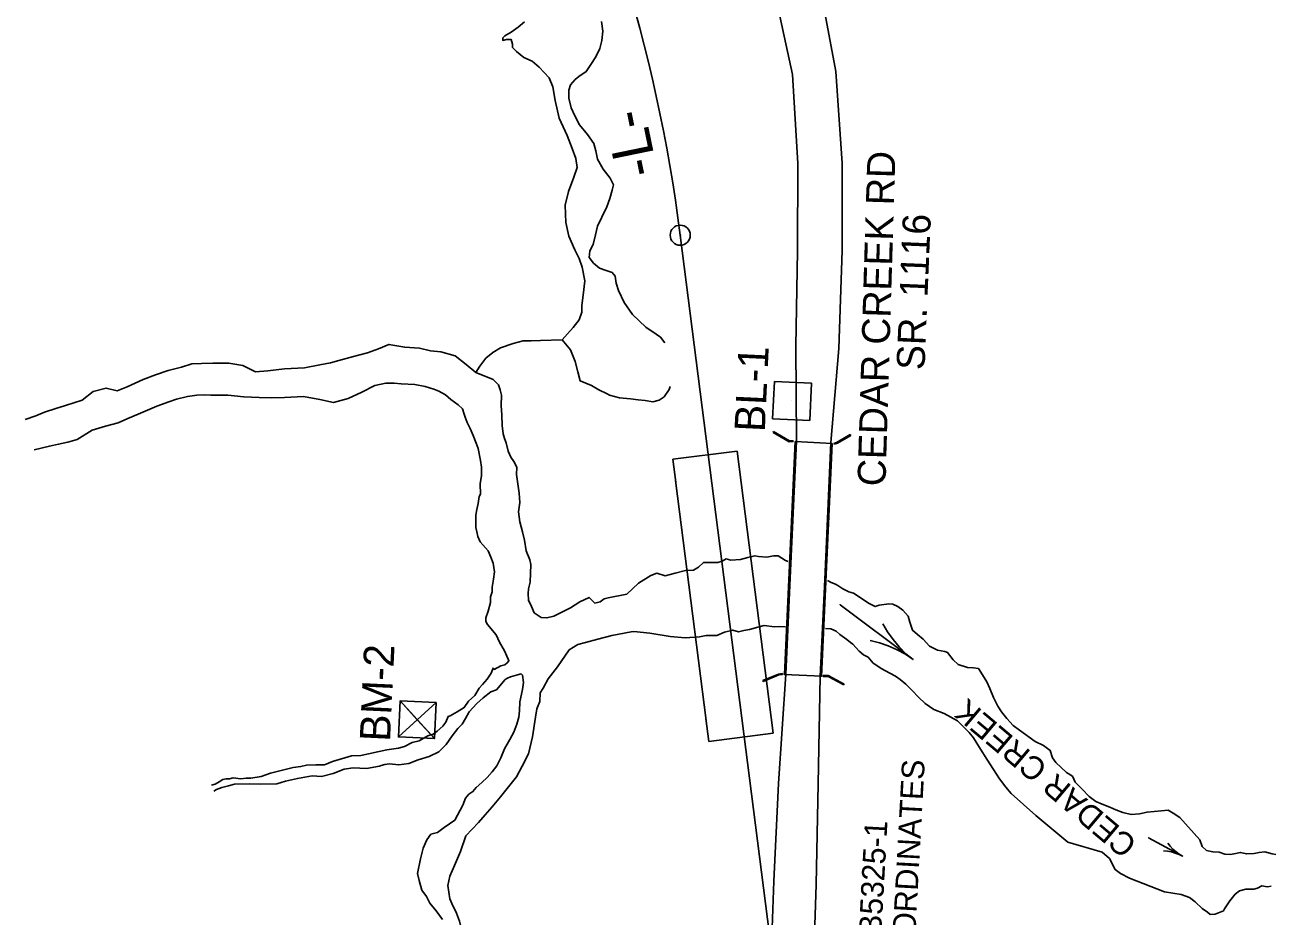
# Model space of a CAD drawing. Extents: x 2167298 to 2168977, y 841960 to 844561.
# Drawn here: x 2167692 to 2168338, y 843259 to 843720 of the extents above; entities that cross this region are included whole.
import ezdxf

# ---------------------------------------------------------------- set-up
doc = ezdxf.new("R2010")
doc.units = 0
for name, color, linetype in [('CTL Bench Mark CELL', 7, 'Continuous'), ('CTL Bench Mark Text', 7, 'Continuous'), ('CTL GPS Vertical Text', 7, 'Continuous'), ('CTL Supplemental Horizontal and Vertical CELL', 7, 'Continuous'), ('CTL Supplemental Horizontal and Vertical Text', 7, 'Continuous'), ('Default', 7, 'Continuous'), ('Exist Hydro River Flow Arrow CELL', 7, 'Continuous'), ('Exist Hydro Stream or Body of Water', 7, 'Continuous'), ('Exist Roads EOP', 7, 'Continuous'), ('Exist Structure Major Bridge WW', 7, 'Continuous'), ('Exist Structure Major Deck Tunnel Box Culvert', 7, 'Continuous'), ('Prop Horizontal Alignment', 7, 'Continuous')]:
    doc.layers.add(name, color=color, linetype=linetype)

msp = doc.modelspace()

# ---------------------------------------------------------------- linework, layer by layer
at = {"layer": 'CTL Bench Mark CELL'}
msp.add_line((2167894.71, 843361.22), (2167894.71, 843361.22), dxfattribs=at)
msp.add_lwpolyline([(2167885.81, 843370.95), (2167904.43, 843370.09), (2167903.57, 843351.47), (2167884.95, 843352.33)], close=True, dxfattribs=at)
for points in [[(2167904.43, 843370.09), (2167884.95, 843352.33), (2167894.69, 843361.21), (2167903.57, 843351.47), (2167885.81, 843370.95)], [(2167894.69, 843361.21), (2167904.43, 843370.09), (2167885.81, 843370.95), (2167894.69, 843361.21)], [(2167894.69, 843361.21), (2167884.95, 843352.33), (2167903.57, 843351.47), (2167894.69, 843361.21)]]:
    msp.add_lwpolyline(points, dxfattribs=at)
at = {"layer": 'CTL Supplemental Horizontal and Vertical CELL'}
msp.add_line((2168088.27, 843525.95), (2168088.27, 843525.95), dxfattribs=at)
msp.add_lwpolyline([(2168079.19, 843535.98), (2168098.4, 843535.08), (2168097.5, 843515.84), (2168078.29, 843516.74)], close=True, dxfattribs=at)
at = {"layer": 'Exist Hydro River Flow Arrow CELL'}
for p, q in [((2168132.03, 843406.48), (2168132.03, 843406.48)), ((2168281.36, 843295.5), (2168281.36, 843295.5))]:
    msp.add_line(p, q, dxfattribs=at)
for points in [[(2168135.27, 843410.79), (2168137.71, 843406.63), (2168140.53, 843402.62), (2168143.7, 843398.84), (2168147.12, 843395.35), (2168150.87, 843392.3), (2168113.19, 843420.65), (2168150.87, 843392.3), (2168146.9, 843395.06), (2168142.6, 843397.38), (2168138.09, 843399.37), (2168133.46, 843400.97), (2168128.79, 843402.17)], [(2168282.44, 843297.52), (2168283.73, 843295.93), (2168285.17, 843294.43), (2168286.74, 843293.05), (2168288.39, 843291.8), (2168290.16, 843290.76), (2168272.55, 843300.25), (2168290.16, 843290.76), (2168288.32, 843291.67), (2168286.37, 843292.37), (2168284.35, 843292.91), (2168282.31, 843293.29), (2168280.27, 843293.49)]]:
    msp.add_lwpolyline(points, dxfattribs=at)
at = {"layer": 'Exist Hydro Stream or Body of Water'}
for points in [[(2167950.09, 843721.86), (2167946.76, 843718.98), (2167943.15, 843716.39), (2167939.99, 843714.65), (2167938.97, 843713.61), (2167938.86, 843712.24), (2167940.86, 843712.7), (2167943.26, 843712.61), (2167943.87, 843710.24), (2167943.84, 843708.58), (2167945.98, 843706.5), (2167949.84, 843703.33), (2167954.09, 843701.49), (2167957.62, 843698.44), (2167962.78, 843692.86), (2167964.7, 843688.26), (2167966.03, 843681.12), (2167968.08, 843672.06), (2167972.13, 843663), (2167974.79, 843656.37), (2167976.69, 843651.24), (2167977.23, 843646.58), (2167975.61, 843641.47), (2167972.86, 843634.2), (2167971.17, 843627), (2167971.53, 843618.07), (2167972.99, 843611.07), (2167976.15, 843604.05), (2167978.33, 843599.46), (2167979.95, 843594.98), (2167981.31, 843587.96), (2167980.47, 843580.67), (2167979.76, 843575.28), (2167979.78, 843571.83), (2167978.28, 843567.88), (2167975.24, 843563.89), (2167972.36, 843560.66), (2167969.51, 843557.55)], [(2167978.25, 843693.48), (2167982, 843696.1), (2167984.46, 843699.74), (2167986.9, 843703.67), (2167989.1, 843708.11), (2167990.02, 843712.12), (2167990.65, 843717.03), (2167989.91, 843722.04)], [(2168005.9, 843570.68), (2168001.56, 843576.87), (2167998.73, 843583), (2167997.53, 843586.82), (2167996.93, 843590.32), (2167995.35, 843592.23), (2167992.27, 843593.34), (2167988.92, 843594.54), (2167985.76, 843597.17), (2167983.47, 843600.03), (2167983.86, 843603.49), (2167985.62, 843606.83), (2167986.76, 843611.77), (2167987.84, 843616.18), (2167990.14, 843620.8), (2167992.59, 843626.29), (2167994.15, 843630.61), (2167995.43, 843634.81), (2167996.14, 843637.63), (2167994.32, 843641.08), (2167990.74, 843645.72), (2167987.76, 843650.82), (2167986.9, 843655.14), (2167985.87, 843658.9), (2167982.62, 843663.67), (2167978.47, 843668.53), (2167976.04, 843673.31), (2167974.29, 843677.45), (2167973.09, 843682.3), (2167972.99, 843686.45), (2167973.89, 843689.31), (2167976.25, 843691.94), (2167978.25, 843693.48)], [(2168005.9, 843570.68), (2168012.8, 843564.03)], [(2168012.8, 843564.03), (2168018.15, 843560.45), (2168020.33, 843558.84), (2168022.55, 843555.99)], [(2167692.02, 843516.38), (2167697.6, 843518.26), (2167702.15, 843520.18), (2167707.97, 843522.06), (2167712.93, 843523.5), (2167721.62, 843526.35), (2167727.15, 843530.89), (2167733.87, 843532.55), (2167739.59, 843531.19), (2167744.75, 843533.29), (2167753.12, 843537), (2167759.4, 843539.37), (2167766.05, 843541.66), (2167772.85, 843543.37), (2167778.14, 843545.14), (2167783.15, 843545.28), (2167789.12, 843545.41), (2167797.32, 843545.42), (2167804.64, 843544.3), (2167811.15, 843541.03), (2167817.41, 843541.43), (2167826.04, 843542.44), (2167836.42, 843543.07), (2167844.3, 843544.57), (2167849.88, 843545.55), (2167854.1, 843546.83), (2167861.78, 843548.94), (2167868.93, 843550.85), (2167874.62, 843552.91), (2167880.07, 843555.18), (2167888.19, 843553.71), (2167895.85, 843553.13), (2167901.59, 843551.78), (2167906.85, 843551.36), (2167914.2, 843549.29), (2167920.04, 843544.76), (2167924.93, 843540.7)], [(2167924.93, 843540.7), (2167927.04, 843543.88), (2167930.06, 843547.97), (2167933.74, 843550.88), (2167937.69, 843553.35), (2167944.2, 843555.67), (2167949.37, 843557.01), (2167953.54, 843557.06), (2167958.43, 843557.09), (2167969.51, 843557.55)], [(2167969.51, 843557.55), (2167973.93, 843552.38), (2167976.22, 843546.28), (2167977.62, 843540.89), (2167978.82, 843536.33), (2167984.64, 843533.92), (2167988.56, 843531.75), (2167992.81, 843529.66), (2167993.96, 843528.85), (2167999.25, 843527.46), (2168004.95, 843527.04)], [(2167924.93, 843540.7), (2167933.96, 843537.02), (2167936.62, 843534.28), (2167937.54, 843531.66), (2167938.3, 843528.85), (2167938.03, 843523.56), (2167938.42, 843518.63), (2167938.56, 843513.33), (2167939, 843509.02), (2167939.78, 843506.51), (2167940.6, 843504.21), (2167941.58, 843499.9), (2167943.07, 843496.86), (2167944.53, 843494.66), (2167946.17, 843491.76), (2167946.03, 843487.87), (2167947.37, 843478.22), (2167947.77, 843473.39), (2167947.03, 843468.64), (2167947.68, 843463.42), (2167948.99, 843458.37), (2167950.11, 843453.98), (2167950.93, 843448.52), (2167952.8, 843443.77), (2167953.42, 843441.5), (2167952.96, 843432.31), (2167952.21, 843428.88), (2167951.93, 843426.45), (2167952.18, 843423.05), (2167953.69, 843419.8), (2167955.13, 843416.5), (2167958.66, 843414.12), (2167961.65, 843413.81), (2167965.29, 843414.78), (2167968.63, 843416.38), (2167973.92, 843419.06), (2167978.69, 843422.15), (2167983.43, 843424.38), (2167986.44, 843421.52), (2167989.15, 843422.11), (2167991.29, 843423.68), (2167993.41, 843424.13)], [(2167696.74, 843500.63), (2167704.61, 843502.65), (2167709.34, 843503.59), (2167714.11, 843504.68), (2167718.93, 843505.99), (2167726.77, 843510.9), (2167733.66, 843512.89), (2167740.1, 843514.64), (2167745.16, 843516.84), (2167750.49, 843519.15), (2167760.17, 843523.16), (2167766.38, 843525.44), (2167770.28, 843526.79), (2167775.89, 843528.21), (2167780.73, 843528.88), (2167784.58, 843529.14), (2167787.97, 843528.98), (2167796.77, 843528.84), (2167805.1, 843528.12), (2167812.97, 843527.63), (2167819.6, 843527.62), (2167826.09, 843527.78), (2167835.99, 843528.15), (2167844.27, 843526.72), (2167851.39, 843525.21), (2167858.91, 843527.28), (2167866.06, 843530.43), (2167872.84, 843533.84), (2167878.37, 843535.1), (2167882.79, 843535.2), (2167886.42, 843534.76), (2167893.5, 843534.39), (2167898.81, 843533.32), (2167903.33, 843532), (2167905.77, 843530.97), (2167909.33, 843529.13), (2167911.96, 843526.67)], [(2168025.44, 843533.35), (2168024.83, 843531.84), (2168022.32, 843528.13), (2168019.64, 843526.36), (2168016.4, 843525.53), (2168012.43, 843526.09), (2168008.91, 843526.46), (2168004.95, 843527.04)], [(2167911.96, 843526.67), (2167915.82, 843523.96), (2167918.04, 843521.91), (2167918.9, 843519.11), (2167919.41, 843517.63), (2167920.51, 843514.79), (2167922.01, 843511.65), (2167923.58, 843508.11), (2167925.09, 843504.08), (2167926.24, 843501.36), (2167927.4, 843495.21), (2167927.94, 843491.68), (2167927.95, 843487.47), (2167927.18, 843483.07), (2167927.42, 843477.84), (2167926.61, 843476.49), (2167926.23, 843473.02), (2167925.42, 843469.78), (2167924.98, 843466.85), (2167924.87, 843464.1), (2167924.97, 843460.58), (2167925.51, 843458.39), (2167926.02, 843455.97), (2167927.12, 843453.06), (2167931.3, 843448.5), (2167932.74, 843445.27), (2167933.9, 843442.08), (2167934.62, 843437.62), (2167934.07, 843433.79), (2167933.31, 843429.76), (2167933.44, 843427.36), (2167932.49, 843424.72), (2167932.48, 843421.81), (2167931.35, 843417.31), (2167930.14, 843413.83), (2167930.19, 843411.91), (2167930.93, 843410.39), (2167935.41, 843405.02), (2167937.18, 843401.24), (2167939.76, 843396.78), (2167940.98, 843394.11), (2167941.61, 843392.55)], [(2168086.38, 843443.03), (2168085, 843443.56), (2168081.15, 843445.84), (2168078.82, 843445.93), (2168075.25, 843445.25), (2168070.95, 843445.57), (2168069.18, 843445.95), (2168065.51, 843444.99), (2168061.67, 843443.99), (2168056.68, 843443.75), (2168054.22, 843444.42), (2168052.19, 843443.14), (2168049.92, 843442.42), (2168046.47, 843442.44), (2168042.56, 843442.45)], [(2168002.89, 843426.13), (2168008.94, 843431.78), (2168015.38, 843435.69), (2168018.54, 843436.94), (2168022.76, 843435.52), (2168028.01, 843436.89), (2168033.32, 843438.4), (2168037.46, 843438.53), (2168040.08, 843439.97), (2168042.56, 843442.45)], [(2168120.17, 843426.6), (2168117.75, 843427.39), (2168114.53, 843428.81), (2168112.05, 843430.66), (2168110.72, 843431.35), (2168108.52, 843432.12), (2168106.66, 843433.09)], [(2168002.89, 843426.13), (2167993.41, 843424.13)], [(2168120.17, 843426.6), (2168125.02, 843423.3), (2168127.76, 843421.45), (2168131.22, 843419.69), (2168133.35, 843420.37), (2168138.32, 843421.1)], [(2168140.44, 843420.89), (2168138.32, 843421.1)], [(2168140.44, 843420.89), (2168142.95, 843419.71), (2168145.58, 843417.89), (2168148.32, 843414.74), (2168149.28, 843411.63), (2168150.61, 843407.45), (2168153.22, 843405.3), (2168156.06, 843402.87), (2168159.28, 843399.3), (2168163.47, 843397.22), (2168167.32, 843396.47), (2168168.75, 843395.89), (2168171.63, 843392.14), (2168174.16, 843389.75), (2168179.06, 843388.15), (2168182.12, 843388.12), (2168184.66, 843387.71), (2168186.68, 843384.37), (2168189.07, 843380.83), (2168190.47, 843377.34), (2168192.51, 843372.74), (2168194.64, 843368.16)], [(2167995.2, 843404.71), (2167988.02, 843402.84), (2167981.54, 843401.15), (2167977.65, 843400.14), (2167973.11, 843397.32), (2167967.18, 843388.51), (2167962.29, 843382.33), (2167959.76, 843377.5), (2167958.16, 843375.04), (2167958.06, 843370.7), (2167956.54, 843366.91)], [(2168005.14, 843406.72), (2167995.2, 843404.71)], [(2168040.55, 843404.11), (2168033.17, 843403.52), (2168025.37, 843404.23), (2168014.86, 843405.98), (2168006.55, 843406.86), (2168005.14, 843406.72)], [(2168040.55, 843404.11), (2168044.03, 843404.79), (2168047.43, 843404.74), (2168049.46, 843404.73), (2168053.44, 843406.5), (2168057.68, 843407.51), (2168060.62, 843406.68), (2168063.37, 843407.25), (2168066.3, 843407.91), (2168070.59, 843409.02), (2168074, 843409.9), (2168079.34, 843409.29), (2168081.73, 843409.35), (2168084.9, 843409.21)], [(2168105.57, 843408.28), (2168108.46, 843408.15), (2168111.08, 843406.9), (2168113.08, 843405.29), (2168116.59, 843402.6), (2168118.52, 843401.21), (2168119.72, 843400.19)], [(2168134.66, 843387.45), (2168130.34, 843390.53), (2168127.61, 843393.56), (2168125.34, 843394.82), (2168122.98, 843396.68), (2168119.72, 843400.19)], [(2167937.83, 843389), (2167939.9, 843389.58), (2167941.18, 843390.56), (2167942.09, 843391.59), (2167941.61, 843392.55)], [(2167937.83, 843389), (2167934.49, 843387.26), (2167933.83, 843387.94), (2167932.85, 843385.34), (2167930.77, 843382.11), (2167928.38, 843379.42), (2167926.66, 843377.6), (2167924.46, 843373.66), (2167921.09, 843370.87), (2167919, 843367.53), (2167915.32, 843365.28), (2167911.69, 843363.31), (2167910.61, 843362.98), (2167909.52, 843359.93), (2167907.87, 843357.86), (2167904.96, 843355.33), (2167902.86, 843353.71), (2167900.16, 843352.85), (2167895.62, 843350.39), (2167892.12, 843349.4)], [(2168136.34, 843386.67), (2168134.66, 843387.45)], [(2168179.87, 843354.63), (2168173.76, 843360.62), (2168166.96, 843364.49), (2168161.66, 843366.58), (2168157.17, 843369.68), (2168153.76, 843372.87), (2168150.46, 843376.26), (2168147.16, 843379.52), (2168144.2, 843381.94), (2168141.75, 843383.79), (2168136.34, 843386.67)], [(2167895.2, 843340.44), (2167900.91, 843342.18), (2167905.77, 843344.57), (2167909.63, 843348.46), (2167912.77, 843352.84), (2167915.73, 843356.65), (2167917.89, 843358.89), (2167919.54, 843361.88), (2167921.55, 843365.31), (2167925.42, 843369.69), (2167928.77, 843372.58), (2167932.74, 843375.65), (2167935.62, 843376.71), (2167940.04, 843382)], [(2167947.68, 843370.45), (2167949.03, 843376.76), (2167949.64, 843380.52), (2167949.02, 843384.2), (2167948.32, 843384.89), (2167946.42, 843384.39), (2167942.82, 843383.44), (2167941.26, 843382.65), (2167940.04, 843382)], [(2167914.14, 843309.37), (2167918.3, 843317.12), (2167919.66, 843320.66), (2167921.39, 843322.76), (2167923.43, 843324.08), (2167925.16, 843326.29), (2167928.1, 843328.75), (2167930.81, 843331.34), (2167933.43, 843334.25), (2167935.82, 843337.43), (2167937.84, 843341.52), (2167939.82, 843346.23), (2167942.53, 843351.08), (2167944.53, 843354.8), (2167946.17, 843358.87), (2167947.22, 843362.54), (2167947.55, 843365.87), (2167947.68, 843370.45)], [(2167956.54, 843366.91), (2167955.7, 843362.51), (2167954.16, 843352.39), (2167952.19, 843343.58), (2167948.92, 843337.28), (2167945.98, 843331.7), (2167937.73, 843321.33), (2167933.37, 843316.25), (2167929.73, 843312.01), (2167926.3, 843308.06), (2167919.76, 843301.26)], [(2168194.64, 843368.16), (2168196.49, 843365.23), (2168199.4, 843361.93), (2168202.57, 843358.19), (2168205.87, 843355.84)], [(2168179.87, 843354.63), (2168182.16, 843351.81), (2168185.78, 843346), (2168188.92, 843340.78), (2168192.48, 843335.5), (2168195.52, 843330.76), (2168198.76, 843326.45), (2168201.48, 843323.17)], [(2168205.87, 843355.84), (2168213.99, 843350.05), (2168218.25, 843347.89), (2168221.64, 843345.33), (2168222.85, 843341.47), (2168224.72, 843339.05), (2168230.19, 843333.88), (2168233.24, 843332.15), (2168234.62, 843328.98), (2168238.25, 843325.28), (2168241.84, 843321.55), (2168245.29, 843319), (2168248.58, 843317.58)], [(2167788.33, 843327.34), (2167790.32, 843327.91), (2167792.38, 843329.06), (2167794.28, 843330.34), (2167795.95, 843330.62), (2167797.71, 843330.63), (2167799.61, 843331.13), (2167803.57, 843330.66), (2167806.24, 843331.01), (2167808.65, 843331), (2167814.07, 843331.95), (2167818.91, 843333.54), (2167824.3, 843334.95), (2167828.51, 843336.05), (2167830.63, 843336.56), (2167834.56, 843337.14), (2167837.52, 843337.74), (2167842.23, 843337.92), (2167846.78, 843337.99), (2167850.89, 843339.62), (2167860.79, 843342.56), (2167865.61, 843342.82), (2167878.96, 843345.62), (2167884.97, 843346.53), (2167888.12, 843347.39)], [(2167888.12, 843347.39), (2167892.12, 843349.4)], [(2167890.37, 843338.69), (2167895.2, 843340.44)], [(2167890.37, 843338.69), (2167885.18, 843337.94), (2167880.4, 843338.45), (2167877.98, 843338.1), (2167875.99, 843337.5), (2167875.26, 843337.17), (2167868.48, 843336.1), (2167861.49, 843336.39), (2167856.89, 843335.71), (2167851.24, 843333.37), (2167845.15, 843331.94), (2167840.34, 843332.22), (2167832.81, 843330.8), (2167826.59, 843329.43), (2167822.07, 843328.07), (2167813.7, 843327.91), (2167808.11, 843328.16), (2167800.29, 843327.91), (2167797.24, 843327.15), (2167793.69, 843326.22), (2167790.9, 843325.13), (2167789.51, 843324.32)], [(2168201.48, 843323.17), (2168214.28, 843311.74), (2168230.88, 843297.96), (2168248.59, 843292.87), (2168252.32, 843289.53), (2168255.24, 843283.8), (2168258.05, 843281.84), (2168262.73, 843279.33), (2168280.77, 843272.36), (2168289.34, 843270.99), (2168293.68, 843269.31), (2168296.57, 843267.15), (2168300.22, 843263.78), (2168303.07, 843261.82), (2168304.3, 843260.57), (2168306.96, 843260.8), (2168311.31, 843262.43), (2168311.76, 843263.44), (2168314.57, 843267.71), (2168317.25, 843271.04), (2168319.48, 843272.83), (2168322.86, 843273.72)], [(2168317.6, 843292.11), (2168314.65, 843291.61), (2168311.91, 843291.8), (2168308.98, 843292.85), (2168305.76, 843293.01), (2168302.54, 843293.63), (2168300.22, 843295.68), (2168299.13, 843299.18), (2168288.76, 843310.69), (2168285.35, 843312.92), (2168282.7, 843314.42), (2168275.41, 843313.88), (2168271.78, 843313.5), (2168267.87, 843312.58), (2168263.61, 843312.26), (2168259.21, 843313.38), (2168255.61, 843314.68), (2168252.46, 843315.99), (2168248.58, 843317.58)], [(2167907.73, 843258.06), (2167904.42, 843262.46), (2167901.24, 843266.42), (2167899.43, 843269.93), (2167897.04, 843273.21), (2167895.59, 843278.19), (2167894.81, 843281.76), (2167896.35, 843289.36), (2167897.69, 843294.83), (2167899.67, 843299.2), (2167901.74, 843302.08), (2167905.14, 843302.96), (2167908.64, 843305.5), (2167914.14, 843309.37)], [(2167919.76, 843301.26), (2167917.03, 843293.13), (2167913.93, 843285.98), (2167911.6, 843280.38), (2167910.53, 843275.5), (2167911.52, 843268.76), (2167912.6, 843266.26), (2167915.01, 843261.26)], [(2168317.6, 843292.11), (2168319.96, 843292.7), (2168323.32, 843291.89), (2168327.09, 843292.03), (2168329.66, 843292.7), (2168332.71, 843293.05), (2168336.37, 843291.99), (2168338.39, 843291.65)], [(2168335.88, 843275.28), (2168334.08, 843274.93), (2168331.07, 843275.49), (2168328.9, 843274.17), (2168326.9, 843273.61), (2168322.86, 843273.72)], [(2167915.01, 843261.26), (2167916.45, 843257.13), (2167917.63, 843252.79), (2167916.61, 843249.72), (2167916.58, 843246.42), (2167916.83, 843243.68), (2167918.83, 843239.9), (2167917.17, 843236.14), (2167915.45, 843232.08), (2167913.97, 843229.18), (2167911.58, 843226.81)]]:
    msp.add_lwpolyline(points, dxfattribs=at)
at = {"layer": 'Exist Roads EOP'}
for points in [[(2168088.8, 842986.5), (2168090.54, 843034.94), (2168092.62, 843085.63), (2168094.79, 843136.47), (2168097.17, 843179.92), (2168099.2, 843228.96), (2168100.75, 843276.01), (2168101.9, 843328.13), (2168102.88, 843383.52), (2168105.26, 843433.67), (2168108.45, 843504.42), (2168112.55, 843553.1), (2168114.28, 843603.6), (2168114.19, 843648.77), (2168111.04, 843696.23), (2168101.28, 843747.73)], [(2168088.8, 842986.5), (2168090.54, 843034.94), (2168092.62, 843085.63), (2168094.79, 843136.47), (2168097.17, 843179.92), (2168099.2, 843228.96), (2168100.75, 843276.01), (2168101.9, 843328.13), (2168102.88, 843383.52), (2168105.26, 843433.67), (2168108.45, 843504.42), (2168112.55, 843553.1), (2168114.28, 843603.6), (2168114.19, 843648.77), (2168111.04, 843696.23), (2168101.28, 843747.73)], [(2168066.47, 842986.79), (2168068.78, 843034.77), (2168070.69, 843085.52), (2168073.1, 843137.29), (2168075.19, 843180.69), (2168077.23, 843229.63), (2168078.87, 843277.87), (2168081.38, 843328.25), (2168085.18, 843384.71), (2168087.31, 843434.46), (2168090.6, 843505.16), (2168090.32, 843554.22), (2168091.17, 843603.38), (2168091.32, 843648.61), (2168088.6, 843694.65), (2168078.62, 843740.74)], [(2168066.47, 842986.79), (2168068.78, 843034.77), (2168070.69, 843085.52), (2168073.1, 843137.29), (2168075.19, 843180.69), (2168077.23, 843229.63), (2168078.87, 843277.87), (2168081.38, 843328.25), (2168085.18, 843384.71), (2168087.31, 843434.46), (2168090.6, 843505.16), (2168090.32, 843554.22), (2168091.17, 843603.38), (2168091.32, 843648.61), (2168088.6, 843694.65), (2168078.62, 843740.74)]]:
    msp.add_lwpolyline(points, dxfattribs=at)
at = {"layer": 'Exist Structure Major Bridge WW'}
for p, q in [((2168078.59, 843509.69), (2168078.84, 843510.12)), ((2168078.59, 843509.69), (2168086.82, 843504.8)), ((2168078.84, 843510.12), (2168086.95, 843505.31)), ((2168111.61, 843504.58), (2168118.4, 843508.58)), ((2168111.83, 843504.13), (2168118.66, 843508.15)), ((2168118.4, 843508.58), (2168118.66, 843508.15)), ((2168086.82, 843504.8), (2168088.91, 843504.9)), ((2168086.95, 843505.31), (2168088.89, 843505.4)), ((2168088.89, 843505.4), (2168088.91, 843504.9)), ((2168109.9, 843503.99), (2168111.61, 843504.58)), ((2168109.9, 843503.99), (2168110.06, 843503.52)), ((2168110.06, 843503.52), (2168111.83, 843504.13)), ((2168081.38, 843384.83), (2168073.28, 843381.47)), ((2168073.28, 843381.47), (2168073.47, 843381.01)), ((2168081.51, 843384.34), (2168073.47, 843381.01)), ((2168083.37, 843385.13), (2168081.38, 843384.83)), ((2168083.44, 843384.64), (2168081.51, 843384.34)), ((2168083.37, 843385.13), (2168083.44, 843384.64)), ((2168107.08, 843384.03), (2168104.38, 843384)), ((2168104.38, 843384), (2168104.39, 843383.5)), ((2168106.96, 843383.53), (2168104.39, 843383.5)), ((2168115.05, 843379.22), (2168106.96, 843383.53)), ((2168115.28, 843379.66), (2168107.08, 843384.03)), ((2168115.28, 843379.66), (2168115.05, 843379.22))]:
    msp.add_line(p, q, dxfattribs=at)
at = {"layer": 'Exist Structure Major Deck Tunnel Box Culvert'}
for p, q in [((2168026.71, 843495.79), (2168059.94, 843500.03)), ((2168028.23, 843483.89), (2168026.71, 843495.79)), ((2168078.57, 843354.22), (2168059.94, 843500.03)), ((2168043.94, 843360.89), (2168028.1, 843484.88)), ((2168045.34, 843349.97), (2168043.82, 843361.88)), ((2168045.34, 843349.97), (2168078.57, 843354.22))]:
    msp.add_line(p, q, dxfattribs=at)
msp.add_lwpolyline([(2168109.04, 843503.94), (2168089.96, 843504.9), (2168084.39, 843384.56), (2168103.6, 843383.66), (2168109.04, 843503.94)], dxfattribs=at)
at = {"layer": 'Prop Horizontal Alignment'}
msp.add_line((2168076.73, 843250.17), (2168030.57, 843611.57), dxfattribs=at)
for radius in [5.19, 0.167]:
    msp.add_circle((2168030.57, 843611.57), radius, dxfattribs=at)
msp.add_arc((2167204.29, 843506.02), 833, 7.27898, 47.10916, dxfattribs=at)

# ---------------------------------------------------------------- texts
at = {"layer": 'CTL Bench Mark Text'}
msp.add_text('BM-2', height=15.692, rotation=87.29593, dxfattribs=at).set_placement((2167880.6, 843349.68))
at = {"layer": 'CTL GPS Vertical Text'}
for s, p in [('LOCALIZED PROJECT COORDINATES', (2168141.54, 843057.59)), ('NCDOT GPS STATION B5325-1', (2168125.23, 843080.7))]:
    msp.add_text(s, height=11.6923, rotation=86.87788, dxfattribs=at).set_placement(p)
at = {"layer": 'CTL Supplemental Horizontal and Vertical Text'}
msp.add_text('BL-1', height=15.692, rotation=87.29593, dxfattribs=at).set_placement((2168074.24, 843509.68))
at = {"layer": 'Default'}
for s, height, rotation, p in [('-L-  ', 21.202, 101.62837, (2168019, 843643.81)), ('CEDAR CREEK RD', 14.4813, 88.27797, (2168136.59, 843481.69)), ('SR. 1116', 14.481, 87.61331, (2168156.75, 843541.67)), ('CEDAR CREEK', 11.968, 139.83458, (2168267.32, 843298.12))]:
    msp.add_text(s, height=height, rotation=rotation, dxfattribs=at).set_placement(p)

doc.saveas('drawing.dxf')
